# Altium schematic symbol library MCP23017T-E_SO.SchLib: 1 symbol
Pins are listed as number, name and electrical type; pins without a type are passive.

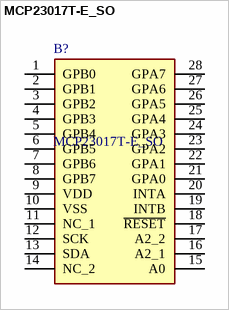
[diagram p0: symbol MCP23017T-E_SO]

## MCP23017T-E_SO
designator B?
Interface - I/O Expanders 16bit Input/Output Exp I2C interface; Manufacturer_Name: Microchip; Manufacturer_Part_Number: MCP23017T-E/SO; Geometry.Height: 2.65mm
footprint SOIC127P1030X265-28N
pins: 1 GPB0, 2 GPB1, 3 GPB2, 4 GPB3, 5 GPB4, 6 GPB5, 7 GPB6, 8 GPB7, 9 VDD, 10 VSS, 11 NC_1, 12 SCK, 13 SDA, 14 NC_2, 15 A0, 16 A2_1, 17 A2_2, 18 ~{RESET}, 19 INTB, 20 INTA, 21 GPA0, 22 GPA1, 23 GPA2, 24 GPA3, 25 GPA4, 26 GPA5, 27 GPA6, 28 GPA7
